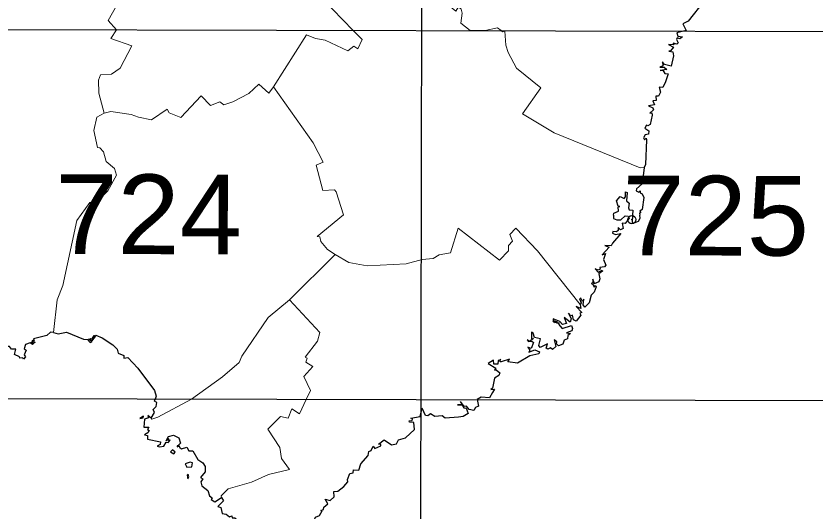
# Model space of a CAD drawing. Extents: x 480264 to 484872, y 4381275 to 4384491.
# Drawn here: x 484571 to 484766.7, y 4383228.3 to 4383349.4 of the extents above; entities that cross this region are included whole.
import ezdxf
from ezdxf.enums import TextEntityAlignment as Align

# ---------------------------------------------------------------- set-up
doc = ezdxf.new("R2010")
doc.units = 0
doc.header["$LTSCALE"] = 4
doc.header["$PDMODE"] = 32
doc.header["$PDSIZE"] = 2
doc.linetypes.add('DOTTED', pattern=[1.5, 0.3, -1.2])
for name, color, linetype, lineweight in [('1', 7, 'Continuous', 13), ('2', 7, 'DOTTED', 13), ('3', 7, 'Continuous', 25)]:
    doc.layers.add(name, color=color, linetype=linetype, lineweight=lineweight)

msp = doc.modelspace()

# ---------------------------------------------------------------- linework, layer by layer
at = {"layer": '1', "lineweight": 25}
for p, q in [((484669.63, 4383074.95), (484670.92, 4383616.9)), ((484254.6, 4383346.9), (484808.84, 4383345.58)), ((484254.38, 4383256.58), (484808.62, 4383255.26))]:
    msp.add_line(p, q, dxfattribs=at)
at = {"layer": '3', "lineweight": 13}
for p, q in [((484682.07, 4383345.87), (484685.71, 4383345.87)), ((484649.08, 4383291.04), (484637.87, 4383280))]:
    msp.add_line(p, q, dxfattribs=at)
for points in [[(484652.31, 4383364.36), (484650.05, 4383363.51), (484650.53, 4383363.07), (484645.9, 4383353.81), (484653.45, 4383345.9)], [(484597.74, 4383355.9), (484593.53, 4383348.32), (484595.55, 4383346.01)], [(484670.42, 4383351.96), (484670.72, 4383351.59), (484671.46, 4383353.31), (484670.54, 4383354.61), (484672.59, 4383356.07), (484673.81, 4383354.62), (484675.47, 4383355.42), (484677.51, 4383353.39), (484676.6, 4383352.57), (484676.82, 4383352.06), (484678.61, 4383350.65), (484679.24, 4383351.68), (484679.84, 4383351.13), (484680.1, 4383350.16), (484679.76, 4383347.67), (484682.07, 4383345.87)], [(484685.71, 4383345.87), (484688.77, 4383346.55), (484689.68, 4383345.88)], [(484592.57, 4383325.63), (484591.22, 4383330.53), (484591.17, 4383333.71), (484591.65, 4383334.99), (484594.36, 4383335.22), (484596.44, 4383336.63), (484599.34, 4383342.12), (484594.19, 4383343.93), (484595.55, 4383346.01)], [(484634, 4383332.1), (484642.03, 4383344.81), (484644.24, 4383343.92), (484646.62, 4383343.54), (484652.13, 4383340.93), (484653.59, 4383342.07), (484654.59, 4383341.36), (484655.63, 4383343.7), (484653.45, 4383345.9)], [(484689.68, 4383345.88), (484690, 4383345.57), (484690.54, 4383345.74), (484690.77, 4383342.29), (484691.34, 4383340.49), (484693.44, 4383336.69), (484699.37, 4383331.84), (484694.85, 4383325.45), (484702.65, 4383320.84), (484723.67, 4383312.3), (484724.63, 4383312.31)], [(484600.92, 4383324.65), (484604.13, 4383324.04), (484607.95, 4383326.61), (484608.46, 4383325.75), (484611.27, 4383324.57), (484616.27, 4383329.86), (484618.55, 4383327.56), (484620.82, 4383328.41), (484621.77, 4383327.65), (484624.01, 4383328.41), (484627.89, 4383330.44), (484630.39, 4383332.73), (484632.84, 4383330.56), (484634, 4383332.1)], [(484634, 4383332.1), (484643.7, 4383318.38), (484646.08, 4383313.65), (484644.41, 4383312.94), (484646.07, 4383306.74), (484648.85, 4383306.9), (484649.29, 4383306.4), (484651.09, 4383300.74)], [(484592.57, 4383325.63), (484590.73, 4383324.63), (484589.99, 4383321.39), (484590.9, 4383317.24), (484591.49, 4383317.14), (484592.35, 4383316.2), (484593.06, 4383313.8), (484595.09, 4383312.13), (484595.53, 4383310.45), (484593.43, 4383306.64), (484591.32, 4383304.59), (484589.03, 4383303.78), (484586.87, 4383300.88)], [(484592.57, 4383325.63), (484594.15, 4383326.08), (484599.17, 4383325.33), (484600.92, 4383324.65)], [(484580.13, 4383271.97), (484581.03, 4383279.99), (484582.4, 4383283.49), (484585.85, 4383299.4), (484586.87, 4383300.88)], [(484649.08, 4383291.04), (484647.16, 4383292.27), (484645.57, 4383294.27), (484645.26, 4383295.37), (484644.65, 4383295.49), (484651.09, 4383300.74)], [(484670.37, 4383289.8), (484673.01, 4383290.09), (484674.47, 4383290.94), (484677.24, 4383291.45), (484679.15, 4383297.49), (484689.29, 4383289.68), (484691.42, 4383291.95), (484691.45, 4383293.24), (484692.46, 4383294.35), (484691.76, 4383295.95), (484693.22, 4383297.53), (484698.58, 4383291.99), (484708.96, 4383278.79)], [(484649.08, 4383291.04), (484652.39, 4383289.11), (484656.85, 4383288.31), (484666.44, 4383288.79), (484670.37, 4383289.8)], [(484637.87, 4383280), (484632.63, 4383275.64), (484626.2, 4383266.15), (484625.54, 4383264.64), (484621.52, 4383261.15), (484613.89, 4383255.64)], [(484637.87, 4383280), (484645.33, 4383272), (484644.73, 4383269.84), (484641.75, 4383265.93), (484642.16, 4383265.67), (484641.9, 4383264.73), (484643.62, 4383263.65), (484641.4, 4383261.18), (484642.99, 4383257.78), (484641.99, 4383255.59)], [(484613.89, 4383255.64), (484605.67, 4383251.28), (484604.16, 4383250.75), (484604.05, 4383251.02)], [(484641.99, 4383255.59), (484640.29, 4383252.08), (484638.45, 4383253.3), (484637.57, 4383251.02), (484635.64, 4383251.39), (484632.59, 4383248.32), (484635.55, 4383243.81), (484635.94, 4383241.15), (484637.89, 4383238.43), (484632.7, 4383237.23), (484628.59, 4383235.33), (484622.9, 4383233.7), (484621.15, 4383231.95), (484621.21, 4383231.57)]]:
    msp.add_lwpolyline(points, dxfattribs=at)
at = {"layer": '3'}
for points in [[(484739.86, 4383354.56), (484738.73, 4383354.6), (484738.66, 4383354.16), (484739.31, 4383353.93), (484739.43, 4383353.22), (484735.42, 4383348.15), (484734.12, 4383347.53), (484734.94, 4383345.88)], [(484734.94, 4383345.88), (484732.61, 4383345.31), (484732.9, 4383344.46), (484734, 4383344.31), (484733.39, 4383343.83), (484732.76, 4383344.12), (484732.56, 4383343.64), (484732.95, 4383342.9), (484732.66, 4383342.56), (484731.71, 4383342.77), (484731.93, 4383342.35), (484730.59, 4383342.47), (484731.8, 4383341.79), (484731.09, 4383340.93)], [(484731.09, 4383340.93), (484730.72, 4383340.79), (484731.65, 4383340.67), (484731.85, 4383339.64), (484731.28, 4383337.17), (484729.62, 4383337.55), (484729.11, 4383338.21), (484729.25, 4383337.2), (484728.52, 4383336.87), (484729.56, 4383336.88), (484730.19, 4383336.37), (484728.59, 4383336.06), (484729.22, 4383336.14), (484729.68, 4383335.36), (484730.49, 4383335.29), (484729.85, 4383333.32)], [(484729.85, 4383333.32), (484729.26, 4383331.9), (484728.3, 4383332.05), (484728.66, 4383330.81), (484728.15, 4383329.82), (484727.47, 4383329.79), (484727.6, 4383328.73), (484726.81, 4383328.64), (484727.21, 4383327.66), (484725.68, 4383327.46), (484726.78, 4383326.95), (484726.95, 4383326.45), (484726.04, 4383325.64), (484726.56, 4383325.7), (484726.61, 4383325.15), (484726.09, 4383322.87), (484725.56, 4383322.58)], [(484725.56, 4383322.58), (484725.19, 4383322.67), (484724.79, 4383321.97), (484725.78, 4383321.33), (484725.68, 4383320.52), (484724.91, 4383320.36), (484724.51, 4383319.57), (484724.74, 4383319.13), (484725.18, 4383319.49), (484725.24, 4383319.1), (484724.95, 4383313.12), (484724.63, 4383312.31)], [(484724.63, 4383312.31), (484724.2, 4383308.34), (484722.79, 4383307.13), (484722.73, 4383306.65), (484723.37, 4383306.35), (484723.71, 4383306.62), (484723.64, 4383306.16), (484724.17, 4383305.93), (484724.6, 4383305.02), (484724.14, 4383302.07), (484723.61, 4383301.68), (484723.8, 4383301.27)], [(484717.19, 4383300.71), (484717.24, 4383301.16), (484718.39, 4383301.65), (484718.3, 4383302.72), (484718.68, 4383302.82), (484718.33, 4383302.91), (484717.9, 4383304.22), (484718.8, 4383305.28), (484719.76, 4383304.74), (484720.09, 4383305.17), (484720.08, 4383306.43), (484720.47, 4383306.25), (484720.37, 4383304.15), (484720.98, 4383303.6), (484720.78, 4383302.48), (484720.95, 4383302.02), (484721.86, 4383301.88), (484721.83, 4383300.71)], [(484717.19, 4383300.71), (484717.17, 4383299.83), (484717.93, 4383299.52), (484718.96, 4383299.51), (484719.97, 4383300.55), (484720.7, 4383300.4), (484720.95, 4383299.96), (484720, 4383298.68), (484719.3, 4383298.73), (484719.48, 4383297.38), (484718.83, 4383297.12), (484718.26, 4383297.7), (484718.28, 4383296.96), (484717.9, 4383296.6), (484716.95, 4383296.68), (484716.92, 4383296.31), (484717.65, 4383295.96), (484718.91, 4383296.23), (484716.91, 4383293.8)], [(484721.83, 4383300.71), (484721.71, 4383299), (484722.05, 4383298.72), (484723.29, 4383299.22), (484723.7, 4383299.93), (484723.58, 4383300.71)], [(484723.8, 4383301.27), (484723.5, 4383301.19), (484723.58, 4383300.71)], [(484716.91, 4383293.8), (484716.6, 4383293.16), (484715.06, 4383293.23), (484716.05, 4383292.87), (484714.37, 4383290.94), (484715.16, 4383291.31), (484714.73, 4383289.81), (484715.27, 4383288.46), (484714.92, 4383288.04), (484713.84, 4383287.84), (484713.9, 4383287.43), (484713.4, 4383287.23), (484712.65, 4383287.56), (484713.42, 4383286.71), (484714.34, 4383287.26), (484714.48, 4383286.99), (484713.54, 4383286.29), (484713.8, 4383285.11), (484713.55, 4383284.4), (484712.44, 4383283.9), (484712.38, 4383284.16)], [(484712.38, 4383284.16), (484712.07, 4383285), (484712.07, 4383284.15), (484711.67, 4383283.98), (484712.13, 4383283.83), (484712.38, 4383283.09), (484712.68, 4383283.45), (484712.9, 4383283.14), (484712.41, 4383281.8), (484711.69, 4383281.14), (484711.23, 4383279.26), (484710.13, 4383278.2), (484709.72, 4383278.71), (484709.93, 4383280.14), (484709.54, 4383279.56), (484709.13, 4383280.33), (484708.85, 4383280.21), (484709.2, 4383279.2), (484708.96, 4383278.79)], [(484708.96, 4383278.79), (484709.17, 4383277.86), (484708.01, 4383278.35), (484709.39, 4383276.82), (484708.94, 4383276.71), (484709.12, 4383276.17), (484708.03, 4383274.77), (484707.38, 4383275.09), (484707.11, 4383276.23), (484706.72, 4383276.01), (484706.13, 4383276.68), (484706.79, 4383275.3), (484706.55, 4383274.53), (484705.04, 4383275.64), (484705.64, 4383274.19), (484704.71, 4383273.92), (484704.02, 4383274.62)], [(484704.02, 4383274.62), (484702.37, 4383275.32), (484702.38, 4383274.55), (484702.65, 4383274.87), (484702.54, 4383274.39), (484703.01, 4383274.79), (484702.83, 4383274.45), (484703.15, 4383274.72), (484703.15, 4383274.31), (484703.36, 4383274.62), (484703.19, 4383274.3), (484703.88, 4383274.31), (484703.7, 4383274.03), (484704.56, 4383272.96), (484706.85, 4383273.71), (484707.12, 4383272.92), (484706.94, 4383272.38), (484705.61, 4383271.87), (484706.65, 4383271.74), (484706, 4383271.19), (484705.92, 4383270.39), (484705.07, 4383270.05), (484704.79, 4383269.08), (484703.71, 4383268.68), (484703.18, 4383269.23)], [(484580.13, 4383271.97), (484579.4, 4383272.01), (484578.47, 4383271.21), (484575.22, 4383270.38), (484575.41, 4383269.85), (484574.9, 4383269.98), (484575.23, 4383269.67), (484574.85, 4383269.82), (484575.09, 4383269.52), (484574.64, 4383269.46), (484575, 4383269.21), (484575.63, 4383269.68), (484575.02, 4383269.06), (484574.4, 4383269.47), (484573.31, 4383269), (484572.98, 4383268), (484573.47, 4383267.68), (484572.95, 4383266.53), (484573.25, 4383265.98), (484572.8, 4383265.46), (484572.65, 4383265.8), (484571.91, 4383265.68)], [(484580.13, 4383271.97), (484581.27, 4383271.63), (484583.35, 4383272.01), (484587.49, 4383270.31), (484588.46, 4383270.25), (484589.12, 4383269.54), (484589.55, 4383269.74), (484588.68, 4383270.33), (484589.16, 4383270.07), (484588.99, 4383270.36), (484589.3, 4383270.18), (484589.13, 4383270.47), (484589.57, 4383270.41), (484590.12, 4383271.26), (484590.32, 4383270.95)], [(484703.18, 4383269.23), (484703.25, 4383269.67), (484702.65, 4383270.14), (484703.04, 4383268.55), (484702.24, 4383267.84), (484701.72, 4383268.23), (484701.07, 4383267.88), (484700.64, 4383268.17), (484701.04, 4383269.16), (484699.21, 4383268.32), (484698.91, 4383268.78), (484699.26, 4383270.42), (484697.8, 4383270.74), (484697.51, 4383271.83), (484697.12, 4383272.02), (484697.06, 4383270.42), (484697.54, 4383270.47), (484696.63, 4383269.77), (484696.05, 4383270.13), (484696.33, 4383269.76)], [(484571.91, 4383265.68), (484571.84, 4383266.04), (484570.63, 4383266.57), (484570.95, 4383267.9), (484569.86, 4383267.86), (484569.39, 4383268.57), (484567.75, 4383268.5), (484566.73, 4383269.24), (484566.44, 4383270.32), (484565.81, 4383270.18), (484565.16, 4383270.8), (484564.28, 4383270.43), (484563.09, 4383271.43)], [(484590.32, 4383270.95), (484589.46, 4383269.88), (484590.53, 4383271.34), (484592.08, 4383270.7), (484594.64, 4383268.95), (484595.71, 4383267.85), (484595.93, 4383266.89), (484597.31, 4383266.36), (484597.31, 4383265.7), (484598.3, 4383265.85), (484600.75, 4383263.22)], [(484696.33, 4383269.76), (484697.17, 4383269.85), (484697.6, 4383269.48), (484697.04, 4383268.08), (484696.19, 4383268.38), (484696.64, 4383267.61), (484696.43, 4383267.12), (484697.92, 4383267.69), (484699.02, 4383267.24), (484698.87, 4383266.77), (484696.65, 4383266.22), (484693.64, 4383264.48), (484691.26, 4383264.81), (484691.68, 4383265.46), (484689.7, 4383264.77), (484689.38, 4383264.77), (484689.53, 4383265.43), (484689.34, 4383265.21)], [(484689.34, 4383265.21), (484688.93, 4383265.13), (484688.87, 4383264.19), (484687.88, 4383264.21), (484687.83, 4383265.16), (484686.46, 4383264.37), (484688.39, 4383263.25), (484688.02, 4383262.78), (484688.47, 4383262.85), (484689.32, 4383262.12), (484689.11, 4383261.45), (484688.01, 4383260.78), (484687.52, 4383258.32), (484687.14, 4383258.05), (484688.04, 4383258.06), (484687.52, 4383257.3)], [(484600.75, 4383263.22), (484604.81, 4383257.77), (484605.27, 4383256.4), (484604.99, 4383255.66)], [(484687.52, 4383257.3), (484686.79, 4383255.97), (484684.75, 4383256.17), (484683.77, 4383255.54)], [(484604.05, 4383251.02), (484604.87, 4383252.38), (484604.52, 4383253.08), (484605.27, 4383253.86), (484605.38, 4383254.81), (484604.83, 4383255.18), (484604.99, 4383255.66)], [(484683.77, 4383255.54), (484684.15, 4383253.94), (484683.38, 4383253.61), (484682.96, 4383252.84), (484681.84, 4383253.08), (484681.15, 4383253.95), (484680.65, 4383253.87), (484679.7, 4383255.07), (484680.03, 4383254.32), (484678.95, 4383254.28), (484680.09, 4383254.21), (484680.54, 4383253.54), (484681.11, 4383253.43), (484681.59, 4383252.17), (484680.36, 4383251.38), (484679.25, 4383251.24)], [(484668.33, 4383249.94), (484667.21, 4383249.99), (484667.13, 4383250.31), (484667.93, 4383250.45), (484667.98, 4383250.87), (484667.6, 4383251.02), (484669.87, 4383251.38), (484670.34, 4383253.44)], [(484679.25, 4383251.24), (484675.94, 4383251.01), (484675.24, 4383251.58), (484673.46, 4383251.39), (484672.36, 4383252.08), (484671.76, 4383251.53), (484671.16, 4383251.64), (484670.34, 4383253.44)], [(484604.05, 4383251.02), (484603.22, 4383251.64), (484603.37, 4383251.1), (484602.43, 4383250.73), (484602.22, 4383248.82), (484603.48, 4383248.8), (484603.14, 4383248.24), (484603.51, 4383247.97), (484603.25, 4383247.39), (484602.37, 4383246.95), (484603.1, 4383246.76), (484603.12, 4383245.82), (484606.32, 4383245.22), (484606.25, 4383244.52), (484605.51, 4383244.18), (484606.07, 4383243.98)], [(484657.89, 4383243.11), (484658.36, 4383244.14), (484658.73, 4383243.61), (484660.22, 4383244.24), (484660.26, 4383244.59), (484659.64, 4383244.63), (484661, 4383245.68), (484662.83, 4383244.45), (484664.09, 4383244.74), (484664.52, 4383245.71), (484666.27, 4383246.18), (484668.43, 4383248.21), (484668.33, 4383249.94)], [(484606.07, 4383243.98), (484607.15, 4383244.15), (484607.72, 4383245.13), (484608.22, 4383245.04), (484608.72, 4383245.61), (484608.31, 4383245.51), (484608.35, 4383245.92), (484607.73, 4383245.48), (484608.29, 4383246.47), (484609.47, 4383246.8), (484610.76, 4383246.15), (484611.24, 4383244.9), (484610.75, 4383244.35), (484611.03, 4383243.8), (484611.48, 4383243.51), (484612.72, 4383243.87), (484613.28, 4383243.01), (484614.26, 4383243.02)], [(484614.26, 4383243.02), (484615.41, 4383240.87), (484616.64, 4383240.07), (484617.24, 4383239.19), (484617.26, 4383237.87), (484616.14, 4383236.5), (484616.65, 4383236.16), (484616.21, 4383235.4), (484616.41, 4383234.47), (484617.91, 4383233.3), (484618.3, 4383232), (484618.92, 4383231.49), (484618.75, 4383231.06), (484619.6, 4383230.52), (484621.21, 4383231.57)], [(484651.21, 4383234.24), (484652.19, 4383235.45), (484652.03, 4383235.97), (484652.65, 4383237.46), (484653.44, 4383237.6), (484653.56, 4383238.39), (484654.88, 4383238.27), (484655.34, 4383239.83), (484657.1, 4383241.82), (484657.28, 4383242.86), (484657.89, 4383243.11)], [(484643.82, 4383225.88), (484644.27, 4383226.77), (484645.22, 4383227.2), (484645.85, 4383228.28), (484645.57, 4383228.4), (484646.16, 4383228.62), (484646.31, 4383229.23), (484647.23, 4383230.01), (484646.64, 4383231.14), (484647.86, 4383230.84), (484648.82, 4383231.74), (484648.75, 4383233.04), (484649.71, 4383233.1), (484651.21, 4383234.24)], [(484621.21, 4383231.57), (484621.74, 4383230.75), (484620.38, 4383229.39), (484621.09, 4383229.1), (484621.44, 4383227.65), (484622.42, 4383227.5), (484623.19, 4383226.82), (484623.76, 4383227.06), (484623.87, 4383226.63), (484624.54, 4383226.63), (484624.8, 4383226.39), (484624.38, 4383225.99), (484626.32, 4383226.18), (484627.2, 4383224.46), (484627, 4383223.81), (484626.23, 4383223.4), (484626.92, 4383223.43), (484626.8, 4383222.74), (484628.6, 4383220.45)]]:
    msp.add_lwpolyline(points, dxfattribs=at)
for points in [[(484602.16, 4383251.48), (484601.25, 4383250.93), (484602.07, 4383251.08)], [(484609.29, 4383243.26), (484608.76, 4383242.73), (484609.55, 4383242.29), (484609.9, 4383242.71)], [(484610.4, 4383244.21), (484610.36, 4383243.96), (484610.68, 4383244.23)], [(484613.56, 4383240.22), (484612.39, 4383239.82), (484612.79, 4383239.02), (484613.97, 4383239.07), (484614.16, 4383240.03)], [(484612.8, 4383237.07), (484613.03, 4383236.13), (484613.23, 4383236.65), (484613.06, 4383237.25)]]:
    msp.add_lwpolyline(points, close=True, dxfattribs=at)
msp.add_point((484721.64, 4383299.59), dxfattribs=at)

# ---------------------------------------------------------------- texts
at = {"layer": '2', "width": 1.05}
for s, p in [('724', (484603.372, 4383291.144)), ('725', (484742.132, 4383290.814))]:
    msp.add_text(s, height=19.5, rotation=359.864, dxfattribs=at).set_placement(p, align=Align.CENTER)

doc.saveas('drawing.dxf')
